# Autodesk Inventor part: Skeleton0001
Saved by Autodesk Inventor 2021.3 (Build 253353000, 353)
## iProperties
Created: 2018-07
Part Number: Skeleton0001
Material: Générique
Document SubType Name: Modeling
Designer: Fabian Perrée
Density: 1 g/cm^3
Appearance: Par défaut
_SkeletonDoc: Frame Skeleton File
_Version: 15.0.0
Author: Fabian Perrée
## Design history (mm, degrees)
sketch "Squelette de référence"
